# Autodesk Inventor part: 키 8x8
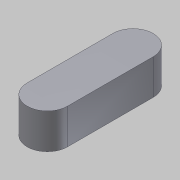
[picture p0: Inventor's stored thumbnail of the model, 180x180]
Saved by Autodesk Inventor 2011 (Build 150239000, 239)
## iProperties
Company: 한국ATC센터
Created: 2014-11
Part Number: 키 8x8
Document SubType Name: Modeling
Designer: KYOUNG IL JANG
Density: 7.86 g/cm^3
Material: 강, 연강
Mass: 10.2483 g
Surface Area: 7.8646 cm^2
Volume: 1.30386 cm^3
Author: KYOUNG IL JANG
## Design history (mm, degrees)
sketch "스케치1"
  geometry: L1 (28.264, -14)-(28.264, -31) reference; L2 (20.264, -31)-(20.264, -14) reference; A1 r 4 centre (24.264, -31) between (20.264, -31) and (28.264, -31) reference; A2 r 4 centre (24.264, -14) between (28.264, -14) and (20.264, -14) reference; 1 further point
extrude "돌출1" new body sketch "스케치1" distance "d0" = 7; taper "d1" = 0 deg
node "솔리드1"
node "참조1"
